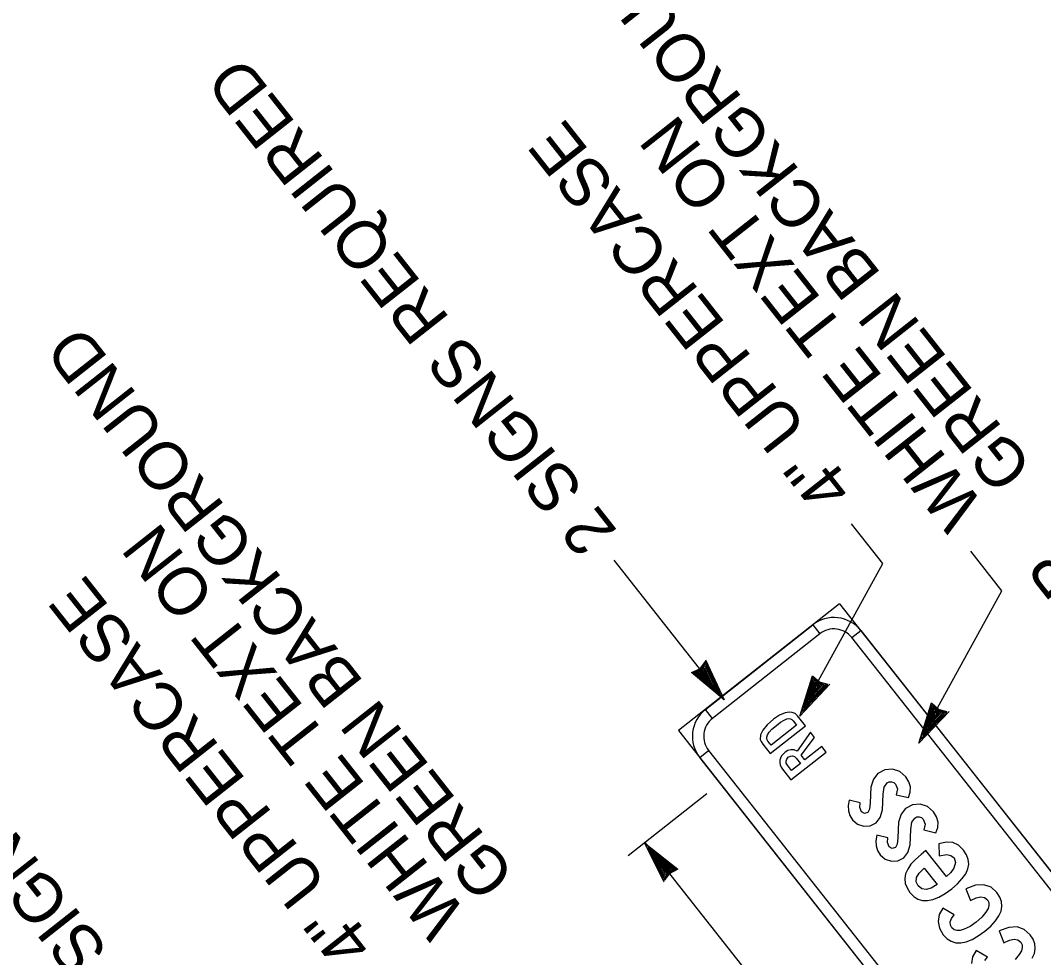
# Model space of a CAD drawing. Extents: x 672438 to 673763, y 1673171 to 1675010.
# Drawn here: x 673288.4 to 673378.2, y 1674792.2 to 1674874.4 of the extents above; entities that cross this region are included whole.
import ezdxf

# ---------------------------------------------------------------- set-up
doc = ezdxf.new("R2010")
doc.units = 0
doc.layers.add('C-ANNO-SYMB', color=7, linetype='Continuous')
doc.layers.add('Level 1', color=7, linetype='Continuous')

msp = doc.modelspace()

# ---------------------------------------------------------------- linework, layer by layer
at = {"layer": 'C-ANNO-SYMB'}
for p, q in [((673360.302, 1674823.256), (673346.166, 1674812.112)), ((673360.302, 1674823.256), (673404.877, 1674766.714)), ((673357.946, 1674821.399), (673358.565, 1674820.613)), ((673361.374, 1674820.281), (673362.159, 1674820.9)), ((673349.141, 1674813.184), (673348.522, 1674813.97)), ((673346.166, 1674812.112), (673390.741, 1674755.57)), ((673348.023, 1674809.756), (673348.809, 1674810.375))]:
    msp.add_line(p, q, dxfattribs=at)
for points in [[(673358.565, 1674820.613), (673349.141, 1674813.184), (673348.522, 1674813.97), (673357.946, 1674821.399), (673358.565, 1674820.613), (673358.565, 1674820.613)], [(673402.234, 1674768.45), (673361.374, 1674820.281), (673362.159, 1674820.9), (673403.02, 1674769.07), (673402.234, 1674768.45), (673402.234, 1674768.45)], [(673348.809, 1674810.375), (673389.669, 1674758.545), (673388.884, 1674757.926), (673348.023, 1674809.756), (673348.809, 1674810.375), (673348.809, 1674810.375)], [(673366.335, 1674806.231), (673366.497, 1674806.705), (673366.51, 1674807.17), (673366.38, 1674807.624), (673366.102, 1674808.07), (673365.582, 1674808.532), (673364.946, 1674808.741), (673364.28, 1674808.685), (673363.661, 1674808.352), (673363.264, 1674807.863), (673363.042, 1674807.161), (673362.979, 1674805.789), (673362.929, 1674805.22), (673362.789, 1674804.936), (673362.486, 1674804.846), (673362.213, 1674804.986), (673362.09, 1674805.361), (673362.115, 1674805.775), (673361.134, 1674806.018), (673361.058, 1674805.533), (673361.082, 1674805.083), (673361.211, 1674804.67), (673361.438, 1674804.296), (673361.88, 1674803.906), (673362.422, 1674803.721), (673362.992, 1674803.755), (673363.508, 1674804.024), (673363.869, 1674804.482), (673364.053, 1674805.157), (673364.112, 1674806.523), (673364.227, 1674807.15), (673364.472, 1674807.523), (673364.651, 1674807.614), (673364.854, 1674807.628), (673365.051, 1674807.563), (673365.206, 1674807.425), (673365.378, 1674806.994), (673365.275, 1674806.485)], [(673368.761, 1674803.152), (673368.924, 1674803.626), (673368.937, 1674804.091), (673368.807, 1674804.546), (673368.529, 1674804.992), (673368.009, 1674805.454), (673367.373, 1674805.663), (673366.707, 1674805.607), (673366.088, 1674805.274), (673365.691, 1674804.784), (673365.469, 1674804.082), (673365.406, 1674802.711), (673365.356, 1674802.142), (673365.216, 1674801.857), (673364.913, 1674801.767), (673364.64, 1674801.908), (673364.517, 1674802.282), (673364.542, 1674802.696), (673363.561, 1674802.94), (673363.485, 1674802.454), (673363.508, 1674802.004), (673363.638, 1674801.591), (673363.865, 1674801.217), (673364.307, 1674800.828), (673364.849, 1674800.642), (673365.419, 1674800.676), (673365.935, 1674800.945), (673366.296, 1674801.404), (673366.48, 1674802.079), (673366.539, 1674803.445), (673366.654, 1674804.071), (673366.899, 1674804.444), (673367.078, 1674804.536), (673367.281, 1674804.549), (673367.478, 1674804.485), (673367.633, 1674804.347), (673367.805, 1674803.916), (673367.702, 1674803.406)], [(673371.784, 1674797.19), (673372.276, 1674797.425), (673372.685, 1674797.516), (673373.02, 1674797.455), (673373.278, 1674797.25), (673373.396, 1674797.025), (673373.411, 1674796.774), (673373.329, 1674796.489), (673373.145, 1674796.179), (673372.782, 1674795.739), (673372.286, 1674795.299), (673371.745, 1674794.925), (673371.226, 1674794.675), (673370.885, 1674794.574), (673370.592, 1674794.561), (673370.354, 1674794.633), (673370.164, 1674794.795), (673370.032, 1674795.053), (673370.019, 1674795.33), (673370.127, 1674795.631), (673370.352, 1674795.951), (673369.35, 1674796.524), (673369.037, 1674795.967), (673368.944, 1674795.37), (673369.069, 1674794.768), (673369.402, 1674794.194), (673369.733, 1674793.852), (673370.098, 1674793.623), (673370.5, 1674793.5), (673370.937, 1674793.486), (673371.413, 1674793.58), (673371.922, 1674793.782), (673372.468, 1674794.094), (673373.05, 1674794.513), (673373.573, 1674794.964), (673373.983, 1674795.407), (673374.284, 1674795.844), (673374.471, 1674796.272), (673374.55, 1674796.692), (673374.515, 1674797.105), (673374.37, 1674797.508), (673374.113, 1674797.908), (673373.588, 1674798.38), (673372.96, 1674798.591), (673372.227, 1674798.543), (673371.387, 1674798.239)]]:
    msp.add_lwpolyline(points, close=True, dxfattribs=at)
for points in [[(673357.305, 1674812.521), (673356.597, 1674813.418), (673356.397, 1674813.606), (673356.152, 1674813.713), (673355.866, 1674813.739), (673355.534, 1674813.684), (673355.017, 1674813.472), (673354.491, 1674813.123), (673353.933, 1674812.628), (673353.554, 1674812.165), (673353.356, 1674811.737), (673353.337, 1674811.343), (673353.413, 1674811.154), (673353.56, 1674810.934), (673354.224, 1674810.092), (673357.305, 1674812.521)], [(673356.527, 1674812.593), (673354.3, 1674810.837), (673354.015, 1674811.198), (673353.925, 1674811.368), (673353.91, 1674811.554), (673353.971, 1674811.754), (673354.108, 1674811.969), (673354.359, 1674812.233), (673354.763, 1674812.574), (673355.112, 1674812.849), (673355.428, 1674813.044), (673355.668, 1674813.147), (673355.834, 1674813.172), (673355.981, 1674813.151), (673356.113, 1674813.085), (673356.226, 1674812.975), (673356.527, 1674812.593)], [(673359.112, 1674810.228), (673358.731, 1674810.711), (673357.265, 1674809.554), (673356.94, 1674809.966), (673358.089, 1674811.525), (673357.741, 1674811.967), (673356.575, 1674810.322), (673356.317, 1674810.428), (673356.033, 1674810.44), (673355.77, 1674810.367), (673355.523, 1674810.218), (673355.348, 1674810.059), (673355.214, 1674809.889), (673355.12, 1674809.709), (673355.066, 1674809.52), (673355.055, 1674809.317), (673355.092, 1674809.116), (673355.175, 1674808.917), (673355.305, 1674808.721), (673356.032, 1674807.799), (673359.112, 1674810.228)], [(673356.859, 1674809.235), (673356.074, 1674808.616), (673355.717, 1674809.068), (673355.62, 1674809.247), (673355.599, 1674809.437), (673355.661, 1674809.617), (673355.802, 1674809.772), (673355.993, 1674809.883), (673356.17, 1674809.908), (673356.337, 1674809.848), (673356.491, 1674809.702), (673356.859, 1674809.235)], [(673369.687, 1674799.3), (673367.883, 1674801.588), (673367.458, 1674801.253), (673366.958, 1674800.816), (673366.561, 1674800.384), (673366.276, 1674799.958), (673366.096, 1674799.537), (673366.029, 1674799.121), (673366.068, 1674798.71), (673366.219, 1674798.305), (673366.474, 1674797.909), (673366.807, 1674797.568), (673367.174, 1674797.334), (673367.579, 1674797.21), (673368.017, 1674797.197), (673368.497, 1674797.292), (673369.009, 1674797.496), (673369.558, 1674797.809), (673370.144, 1674798.232), (673370.662, 1674798.68), (673371.07, 1674799.121), (673371.368, 1674799.555), (673371.552, 1674799.981), (673371.63, 1674800.401), (673371.593, 1674800.815), (673371.445, 1674801.223), (673371.186, 1674801.621), (673370.741, 1674802.05), (673370.23, 1674802.288), (673369.654, 1674802.336), (673369.008, 1674802.191), (673369.045, 1674801.111), (673369.719, 1674801.239), (673370.075, 1674801.167), (673370.341, 1674800.955), (673370.478, 1674800.552), (673370.322, 1674800.052), (673370.055, 1674799.668), (673369.687, 1674799.3)], [(673368.86, 1674798.609), (673368.343, 1674798.287), (673367.893, 1674798.159), (673367.512, 1674798.223), (673367.2, 1674798.479), (673367.031, 1674798.832), (673367.062, 1674799.212), (673367.298, 1674799.612), (673367.734, 1674800.038), (673368.86, 1674798.609)], [(673377.207, 1674792.137), (673377.393, 1674792.565), (673377.472, 1674792.985), (673377.437, 1674793.398), (673377.292, 1674793.801), (673377.035, 1674794.202), (673376.51, 1674794.673), (673375.882, 1674794.885), (673375.149, 1674794.837), (673374.309, 1674794.532), (673374.706, 1674793.484), (673375.198, 1674793.718), (673375.608, 1674793.809), (673375.943, 1674793.748), (673376.2, 1674793.543), (673376.319, 1674793.319), (673376.333, 1674793.067), (673376.252, 1674792.782), (673376.067, 1674792.472), (673375.704, 1674792.032)], [(673373.05, 1674791.924), (673373.274, 1674792.244), (673372.272, 1674792.817), (673371.959, 1674792.26), (673371.866, 1674791.664)]]:
    msp.add_lwpolyline(points, dxfattribs=at)
for centre, radius, start, end in [((673359.803, 1674819.043), 3, 38.2506, 128.25081), ((673359.803, 1674819.043), 2, 38.2506, 128.25081), ((673350.379, 1674811.614), 3, 128.25054, 218.25075), ((673350.379, 1674811.614), 2, 128.25054, 218.25075)]:
    msp.add_arc(centre, radius, start, end, dxfattribs=at)
at = {"layer": 'Level 1'}
for p, q in [((673350.174, 1674814.824), (673340.516, 1674827.075)), ((673348.035, 1674817.512), (673348.522, 1674818.173)), ((673348.522, 1674818.173), (673348.454, 1674817.955)), ((673348.543, 1674818.32), (673350.174, 1674814.824)), ((673347.314, 1674817.205), (673348.082, 1674817.581)), ((673347.462, 1674817.183), (673348.035, 1674817.512)), ((673347.631, 1674817.177), (673347.894, 1674817.31)), ((673347.762, 1674817.176), (673348.475, 1674817.842)), ((673347.894, 1674817.31), (673348.475, 1674817.842)), ((673347.897, 1674817.214), (673348.412, 1674817.664)), ((673348.307, 1674817.585), (673348.028, 1674817.215)), ((673348.04, 1674817.156), (673348.369, 1674817.503)), ((673348.082, 1674817.581), (673348.397, 1674817.816)), ((673348.166, 1674817.118), (673348.318, 1674817.396)), ((673348.311, 1674817.227), (673348.307, 1674817.585)), ((673348.318, 1674817.396), (673348.578, 1674816.874)), ((673348.369, 1674817.503), (673348.866, 1674816.532)), ((673348.397, 1674817.816), (673348.591, 1674818.127)), ((673348.412, 1674817.664), (673349.127, 1674816.139)), ((673348.454, 1674817.955), (673348.549, 1674817.962)), ((673348.475, 1674817.842), (673349.457, 1674815.698)), ((673348.475, 1674817.842), (673349.579, 1674815.624)), ((673348.549, 1674817.962), (673349.912, 1674815.089)), ((673348.591, 1674818.127), (673349.823, 1674815.252)), ((673350.174, 1674814.824), (673347.314, 1674817.205)), ((673349.943, 1674815.046), (673347.462, 1674817.183)), ((673349.675, 1674815.403), (673347.631, 1674817.177)), ((673349.457, 1674815.698), (673347.762, 1674817.176)), ((673349.579, 1674815.624), (673347.897, 1674817.214)), ((673348.028, 1674817.215), (673348.776, 1674816.693)), ((673349.127, 1674816.139), (673348.04, 1674817.156)), ((673348.866, 1674816.532), (673348.166, 1674817.118)), ((673348.244, 1674817.147), (673348.311, 1674817.227)), ((673348.578, 1674816.874), (673348.244, 1674817.147)), ((673348.776, 1674816.693), (673348.871, 1674816.438)), ((673356.802, 1674813.387), (673357.919, 1674816.937)), ((673356.921, 1674813.685), (673357.956, 1674816.791)), ((673357.149, 1674814.069), (673358.014, 1674816.633)), ((673357.317, 1674814.241), (673358.149, 1674816.401)), ((673357.339, 1674814.382), (673358.063, 1674816.511)), ((673357.919, 1674816.937), (673358.559, 1674816.37)), ((673357.956, 1674816.791), (673358.477, 1674816.387)), ((673358.014, 1674816.633), (673358.236, 1674816.441)), ((673358.063, 1674816.511), (673358.949, 1674816.105)), ((673358.149, 1674816.401), (673358.761, 1674816.095)), ((673358.236, 1674816.441), (673358.949, 1674816.105)), ((673358.477, 1674816.387), (673359.273, 1674816.188)), ((673358.559, 1674816.37), (673358.896, 1674816.168)), ((673359.457, 1674816.186), (673356.802, 1674813.387)), ((673359.088, 1674816.082), (673356.948, 1674813.73)), ((673359.257, 1674816.106), (673357.065, 1674813.874)), ((673358.949, 1674816.105), (673357.317, 1674814.241)), ((673358.949, 1674816.105), (673357.339, 1674814.382)), ((673357.622, 1674814.855), (673358.15, 1674816.247)), ((673358.761, 1674816.095), (673357.622, 1674814.855)), ((673357.886, 1674815.246), (673358.163, 1674816.116)), ((673358.595, 1674816.074), (673357.886, 1674815.246)), ((673358.2, 1674816.28), (673358.001, 1674815.39)), ((673358.477, 1674816.081), (673358.093, 1674815.642)), ((673358.093, 1674815.642), (673358.218, 1674816.055)), ((673358.15, 1674816.247), (673358.595, 1674816.074)), ((673358.163, 1674816.116), (673358.477, 1674816.081)), ((673358.648, 1674816.163), (673358.2, 1674816.28)), ((673358.218, 1674816.055), (673358.318, 1674816.024)), ((673358.318, 1674816.024), (673358.648, 1674816.163)), ((673358.896, 1674816.168), (673359.257, 1674816.106)), ((673359.046, 1674816.168), (673359.088, 1674816.082)), ((673357.801, 1674815.205), (673357.589, 1674814.751)), ((673357.589, 1674814.751), (673357.92, 1674815.101)), ((673358.001, 1674815.39), (673357.801, 1674815.205)), ((673357.131, 1674813.832), (673357.724, 1674814.517)), ((673357.724, 1674814.517), (673357.149, 1674814.069)), ((673367.252, 1674810.999), (673368.368, 1674814.549)), ((673369.906, 1674813.799), (673367.252, 1674810.999)), ((673367.37, 1674811.298), (673368.405, 1674814.404)), ((673369.537, 1674813.694), (673367.397, 1674811.342)), ((673369.706, 1674813.718), (673367.514, 1674811.486)), ((673367.598, 1674811.681), (673368.463, 1674814.246)), ((673367.766, 1674811.853), (673368.598, 1674814.014)), ((673369.398, 1674813.718), (673367.766, 1674811.853)), ((673367.788, 1674811.994), (673368.512, 1674814.124)), ((673369.398, 1674813.718), (673367.788, 1674811.994)), ((673368.071, 1674812.467), (673368.599, 1674813.859)), ((673369.21, 1674813.708), (673368.071, 1674812.467)), ((673368.335, 1674812.858), (673368.612, 1674813.728)), ((673369.045, 1674813.686), (673368.335, 1674812.858)), ((673368.368, 1674814.549), (673369.008, 1674813.982)), ((673368.405, 1674814.404), (673368.927, 1674813.999)), ((673368.649, 1674813.892), (673368.45, 1674813.003)), ((673368.463, 1674814.246), (673368.685, 1674814.053)), ((673368.512, 1674814.124), (673369.398, 1674813.718)), ((673368.927, 1674813.694), (673368.542, 1674813.254)), ((673368.598, 1674814.014), (673369.21, 1674813.708)), ((673368.599, 1674813.859), (673369.045, 1674813.686)), ((673368.612, 1674813.728), (673368.927, 1674813.694)), ((673369.097, 1674813.775), (673368.649, 1674813.892)), ((673368.685, 1674814.053), (673369.398, 1674813.718)), ((673368.767, 1674813.636), (673369.097, 1674813.775)), ((673368.927, 1674813.999), (673369.723, 1674813.8)), ((673369.008, 1674813.982), (673369.345, 1674813.78)), ((673369.345, 1674813.78), (673369.706, 1674813.718)), ((673369.495, 1674813.78), (673369.537, 1674813.694)), ((673368.25, 1674812.818), (673368.038, 1674812.363)), ((673368.45, 1674813.003), (673368.25, 1674812.818)), ((673368.542, 1674813.254), (673368.667, 1674813.667)), ((673368.667, 1674813.667), (673368.767, 1674813.636)), ((673367.58, 1674811.445), (673368.173, 1674812.129)), ((673368.173, 1674812.129), (673367.598, 1674811.681)), ((673368.038, 1674812.363), (673368.37, 1674812.714)), ((673348.656, 1674806.576), (673341.752, 1674801.133)), ((673344.899, 1674798.81), (673343.196, 1674802.271)), ((673343.196, 1674802.271), (673346.104, 1674799.95)), ((673359.186, 1674782.058), (673343.23, 1674802.298)), ((673343.555, 1674801.851), (673343.432, 1674802.054)), ((673343.432, 1674802.054), (673345.956, 1674799.968)), ((673344.885, 1674799.168), (673343.463, 1674802.012)), ((673343.463, 1674802.012), (673343.493, 1674801.804)), ((673343.493, 1674801.804), (673343.918, 1674801.005)), ((673344.847, 1674799.002), (673343.555, 1674801.851)), ((673343.918, 1674801.005), (673343.707, 1674801.702)), ((673343.707, 1674801.702), (673345.787, 1674799.971)), ((673344.958, 1674799.289), (673343.807, 1674801.483)), ((673343.807, 1674801.483), (673345.522, 1674799.928)), ((673344.958, 1674799.289), (673343.931, 1674801.412)), ((673343.931, 1674801.412), (673345.656, 1674799.969)), ((673344.532, 1674800.684), (673344.184, 1674801.046)), ((673344.184, 1674801.046), (673344.392, 1674800.61)), ((673345.016, 1674799.468), (673344.27, 1674800.978)), ((673344.27, 1674800.978), (673345.378, 1674799.984)), ((673344.633, 1674800.431), (673344.532, 1674800.684)), ((673345.056, 1674799.63), (673344.539, 1674800.591)), ((673344.539, 1674800.591), (673345.251, 1674800.019)), ((673345.391, 1674799.925), (673344.633, 1674800.431)), ((673345.105, 1674799.738), (673344.834, 1674800.255)), ((673344.834, 1674800.255), (673345.174, 1674799.989)), ((673345.035, 1674799.316), (673344.847, 1674799.002)), ((673345.391, 1674799.627), (673344.917, 1674798.957)), ((673345.656, 1674799.969), (673344.958, 1674799.289)), ((673345.527, 1674799.833), (673344.958, 1674799.289)), ((673345.522, 1674799.928), (673345.016, 1674799.468)), ((673345.345, 1674799.558), (673345.035, 1674799.316)), ((673345.378, 1674799.984), (673345.056, 1674799.63)), ((673345.251, 1674800.019), (673345.105, 1674799.738)), ((673345.174, 1674799.989), (673345.109, 1674799.907)), ((673345.109, 1674799.907), (673345.12, 1674799.549)), ((673345.12, 1674799.549), (673345.391, 1674799.925)), ((673346.104, 1674799.95), (673345.345, 1674799.558)), ((673345.956, 1674799.968), (673345.391, 1674799.627)), ((673345.787, 1674799.971), (673345.527, 1674799.833)), ((673344.981, 1674799.176), (673344.885, 1674799.168))]:
    msp.add_line(p, q, dxfattribs=at)
for points in [[(673357.94, 1674815.594), (673364.102, 1674826.771), (673361.357, 1674830.254)], [(673368.389, 1674813.207), (673374.552, 1674824.383), (673371.806, 1674827.866)]]:
    msp.add_lwpolyline(points, dxfattribs=at)

# ---------------------------------------------------------------- texts
for s, p in [('GREEN BACKGROUND', (673377.379, 1674835.221)), ('2 SIGNS REQUIRED', (673340.873, 1674829.613)), ('WHITE TEXT ON', (673373.085, 1674831.836)), ('4" UPPERCASE', (673361.669, 1674833.461)), ('GREEN BACKGROUND', (673331.965, 1674799.419)), ('WHITE TEXT ON', (673327.671, 1674796.033)), ('1 SIGN REQUIRED', (673299.156, 1674789.122)), ('BORDER STRIP', (673405.943, 1674795.715)), ('4" UPPERCASE', (673319.58, 1674793.442))]:
    msp.add_text(s, height=4.2, rotation=128.25054, dxfattribs=at).set_placement(p)

doc.saveas('drawing.dxf')
